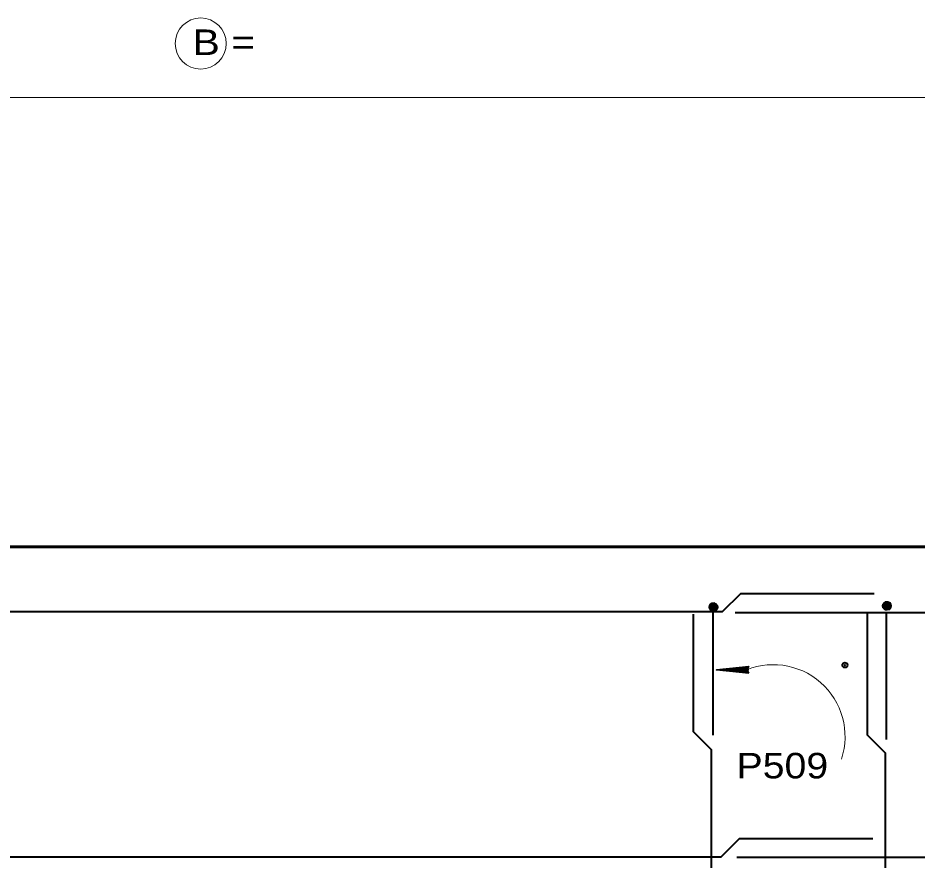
# Model space of a CAD drawing. Extents: x 3.64 to 6.84, y -0.8 to 1.19.
# Drawn here: x 4.238 to 4.5316, y 0.1724 to 0.4473 of the extents above; entities that cross this region are included whole.
import ezdxf

# ---------------------------------------------------------------- set-up
doc = ezdxf.new("R2010")
doc.units = 0
doc.header["$LTSCALE"] = 0.0033
doc.header["$PDMODE"] = 32
doc.header["$PDSIZE"] = 0.00165
doc.layers.add('1', color=7, linetype='Continuous', lineweight=40)

msp = doc.modelspace()

# ---------------------------------------------------------------- linework, layer by layer
at = {"layer": '1', "lineweight": 60}
for p, q in [((4.02775, 0.274583), (4.30575, 0.274583)), ((4.271, 0.274583), (4.611083, 0.274583))]:
    msp.add_line(p, q, dxfattribs=at)
at = {"layer": '1'}
for p, q in [((4.464167, 0.254083), (4.4645, 0.256)), ((4.464333, 0.254), (4.464667, 0.256)), ((4.464417, 0.256083), (4.465917, 0.256)), ((4.464417, 0.254), (4.46475, 0.256)), ((4.464417, 0.255917), (4.465917, 0.255833)), ((4.464417, 0.255833), (4.465917, 0.25575)), ((4.464417, 0.25575), (4.465917, 0.255667)), ((4.464417, 0.255667), (4.465917, 0.255583)), ((4.464417, 0.255583), (4.465917, 0.2555)), ((4.464417, 0.2555), (4.465917, 0.255417)), ((4.4645, 0.254), (4.464917, 0.256)), ((4.464583, 0.254), (4.465, 0.256)), ((4.46475, 0.254), (4.465083, 0.255917)), ((4.464833, 0.253917), (4.465167, 0.255917)), ((4.464917, 0.253917), (4.465333, 0.255917)), ((4.465, 0.253917), (4.465417, 0.255833)), ((4.465083, 0.253917), (4.4655, 0.255833)), ((4.46525, 0.253833), (4.465667, 0.255833)), ((4.4655, 0.253833), (4.465833, 0.255833)), ((4.465583, 0.253833), (4.465917, 0.25575)), ((4.465667, 0.253833), (4.466, 0.25575)), ((4.46575, 0.25375), (4.466083, 0.25575)), ((4.520833, 0.2545), (4.521167, 0.256417)), ((4.521, 0.254417), (4.521333, 0.256417)), ((4.521083, 0.2565), (4.522583, 0.256417)), ((4.521083, 0.254417), (4.521417, 0.256417)), ((4.521083, 0.256333), (4.522583, 0.25625)), ((4.521083, 0.25625), (4.522583, 0.256167)), ((4.521083, 0.256167), (4.522583, 0.256083)), ((4.521083, 0.256083), (4.522583, 0.256)), ((4.521083, 0.256), (4.522583, 0.255917)), ((4.521083, 0.255917), (4.522583, 0.255833)), ((4.521083, 0.255833), (4.522583, 0.25575)), ((4.521083, 0.255833), (4.522583, 0.25575)), ((4.521083, 0.25575), (4.522583, 0.255583)), ((4.521083, 0.255583), (4.522583, 0.255417)), ((4.521167, 0.254417), (4.521583, 0.256417)), ((4.52125, 0.254417), (4.521667, 0.256417)), ((4.521417, 0.254417), (4.52175, 0.256333)), ((4.5215, 0.254333), (4.521833, 0.256333)), ((4.521583, 0.254333), (4.522, 0.256333)), ((4.521667, 0.254333), (4.522083, 0.25625)), ((4.52175, 0.254333), (4.522167, 0.25625)), ((4.521917, 0.25425), (4.522333, 0.25625)), ((4.522167, 0.25425), (4.5225, 0.25625)), ((4.52225, 0.25425), (4.522583, 0.256167)), ((4.522333, 0.25425), (4.522667, 0.256167)), ((4.522417, 0.254167), (4.52275, 0.256167)), ((4.464333, 0.255), (4.465833, 0.254917)), ((4.464333, 0.254917), (4.465833, 0.254833)), ((4.464333, 0.254833), (4.465833, 0.25475)), ((4.464333, 0.25475), (4.465833, 0.254667)), ((4.464333, 0.254667), (4.465833, 0.254583)), ((4.464333, 0.254583), (4.465833, 0.2545)), ((4.464333, 0.2545), (4.465833, 0.254417)), ((4.464333, 0.254333), (4.465833, 0.25425)), ((4.464333, 0.25425), (4.465833, 0.254167)), ((4.464333, 0.254167), (4.465833, 0.254083)), ((4.464333, 0.254083), (4.465833, 0.254)), ((4.464333, 0.254), (4.465833, 0.253917)), ((4.464417, 0.255417), (4.465917, 0.255333)), ((4.464417, 0.255417), (4.465917, 0.255333)), ((4.464417, 0.255333), (4.465917, 0.255167)), ((4.464417, 0.255167), (4.465917, 0.255)), ((4.464917, 0.253083), (4.464917, 0.213167)), ((4.472167, 0.253167), (4.590833, 0.253167)), ((4.521, 0.255417), (4.5225, 0.255333)), ((4.521, 0.255333), (4.5225, 0.25525)), ((4.521, 0.25525), (4.5225, 0.255167)), ((4.521, 0.255167), (4.5225, 0.255083)), ((4.521, 0.255083), (4.5225, 0.255)), ((4.521, 0.255), (4.5225, 0.254917)), ((4.521, 0.254917), (4.5225, 0.254833)), ((4.521, 0.25475), (4.5225, 0.254667)), ((4.521, 0.254667), (4.5225, 0.254583)), ((4.521, 0.254583), (4.5225, 0.2545)), ((4.521, 0.2545), (4.5225, 0.254417)), ((4.521, 0.254417), (4.5225, 0.254333)), ((4.521583, 0.253167), (4.521583, 0.211667)), ((4.47275, 0.17325), (4.589083, 0.17325))]:
    msp.add_line(p, q, dxfattribs=at)
at = {"layer": '1', "lineweight": 35}
for p, q in [((4.476417, 0.2355), (4.469083, 0.234667)), ((4.476417, 0.235333), (4.469083, 0.234583)), ((4.476417, 0.23525), (4.469083, 0.234417)), ((4.4765, 0.235083), (4.469167, 0.234333)), ((4.476667, 0.234417), (4.466083, 0.234417)), ((4.476417, 0.233583), (4.468583, 0.234583)), ((4.476417, 0.233583), (4.468583, 0.234417)), ((4.476417, 0.233417), (4.468583, 0.234333)), ((4.476417, 0.233417), (4.468583, 0.234333)), ((4.476417, 0.2335), (4.468583, 0.234333))]:
    msp.add_line(p, q, dxfattribs=at)
at = {"layer": '1', "lineweight": 13}
msp.add_lwpolyline([(4.027083, 0.42125), (4.329917, 0.42125), (4.610417, 0.42125)], dxfattribs=at)
at = {"layer": '1'}
for points in [[(4.517583, 0.25925), (4.473917, 0.25925), (4.468, 0.253333), (4.25325, 0.253333), (4.158333, 0.253333), (4.152417, 0.25925), (4.109083, 0.25925)], [(4.465167, 0.253583), (4.464833, 0.256167), (4.464333, 0.253833), (4.465417, 0.256167), (4.465833, 0.25375), (4.466167, 0.25575), (4.464083, 0.25575), (4.466417, 0.254833), (4.463833, 0.255083), (4.466167, 0.254083), (4.463833, 0.254417), (4.466417, 0.25525), (4.464667, 0.253667), (4.4645, 0.256083), (4.466333, 0.254417), (4.463917, 0.2555), (4.464333, 0.253833), (4.465833, 0.25375), (4.466417, 0.254833), (4.466167, 0.25575), (4.465417, 0.256167), (4.4645, 0.256083), (4.463917, 0.2555), (4.465, 0.254833), (4.465917, 0.256), (4.466167, 0.254083), (4.465, 0.254833), (4.4645, 0.25375), (4.463833, 0.25475), (4.464917, 0.254833), (4.466167, 0.255667), (4.464917, 0.253667), (4.464583, 0.255), (4.464083, 0.25575)], [(4.521833, 0.254), (4.5215, 0.256583), (4.521, 0.25425), (4.522083, 0.256583), (4.5225, 0.254167), (4.522833, 0.256167), (4.52075, 0.256167), (4.523083, 0.25525), (4.5205, 0.2555), (4.522833, 0.2545), (4.5205, 0.254833), (4.523083, 0.255667), (4.521333, 0.254083), (4.521167, 0.2565), (4.523, 0.254833), (4.520583, 0.255917), (4.521, 0.25425), (4.5225, 0.254167), (4.523083, 0.25525), (4.522833, 0.256167), (4.522083, 0.256583), (4.521167, 0.2565), (4.520583, 0.255917), (4.521667, 0.25525), (4.522583, 0.256417), (4.522833, 0.2545), (4.521667, 0.25525), (4.521167, 0.254167), (4.5205, 0.255167), (4.521583, 0.25525), (4.522833, 0.256083), (4.521583, 0.254083), (4.52125, 0.255417), (4.52075, 0.256167)], [(4.4585, 0.252583), (4.4585, 0.214333), (4.464417, 0.208417), (4.464417, 0.000083), (4.4585, -0.005833), (4.4585, -0.052083)], [(4.515333, 0.253167), (4.515333, 0.21325), (4.52125, 0.207333), (4.52125, -0.001), (4.515333, -0.006917), (4.515333, -0.053167)], [(4.517167, 0.17925), (4.4735, 0.17925), (4.467583, 0.173333), (4.252833, 0.173333), (4.157917, 0.173333), (4.152, 0.17925), (4.108667, 0.17925)]]:
    msp.add_lwpolyline(points, dxfattribs=at)
at = {"layer": '1', "lineweight": 35}
for points in [[(4.476667, 0.233333), (4.466083, 0.234417), (4.476667, 0.235583), (4.476083, 0.234417)], [(4.475917, 0.234333), (4.47125, 0.23425), (4.47125, 0.234333), (4.472167, 0.234333), (4.475917, 0.23425), (4.472917, 0.234167), (4.476083, 0.234083), (4.473833, 0.234), (4.476083, 0.233917), (4.472583, 0.234167), (4.467917, 0.234333), (4.468833, 0.234583), (4.467583, 0.234583), (4.475917, 0.234583), (4.4735, 0.23475), (4.476083, 0.23475), (4.47075, 0.234333), (4.476083, 0.235)]]:
    msp.add_lwpolyline(points, close=True, dxfattribs=at)
msp.add_lwpolyline([(4.475917, 0.234333), (4.476333, 0.233583), (4.476083, 0.233833), (4.475917, 0.234167), (4.475667, 0.234083), (4.475833, 0.23375), (4.476, 0.2345), (4.476167, 0.235), (4.476417, 0.235417)], dxfattribs=at)
at = {"layer": '1', "lineweight": 13}
msp.add_circle((4.297667, 0.438917), 0.008333, dxfattribs=at)
at = {"layer": '1'}
for centre in [(4.465117, 0.254917), (4.521783, 0.255333)]:
    msp.add_circle(centre, 0.00132, dxfattribs=at)
at = {"layer": '1', "lineweight": 13}
msp.add_arc((4.484695, 0.212712), 0.023415, 341.63221, 116.03756, dxfattribs=at)
at = {"layer": '1'}
msp.add_point((4.508083, 0.236), dxfattribs=at)

# ---------------------------------------------------------------- texts
for s, width, p in [('B =      ', 1.2, (4.295, 0.435167)), ('P509', 1.15, (4.472667, 0.199))]:
    msp.add_text(s, height=0.008334, dxfattribs=dict(at, width=width)).set_placement(p)

doc.saveas('drawing.dxf')
